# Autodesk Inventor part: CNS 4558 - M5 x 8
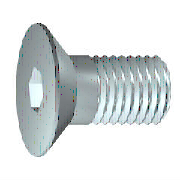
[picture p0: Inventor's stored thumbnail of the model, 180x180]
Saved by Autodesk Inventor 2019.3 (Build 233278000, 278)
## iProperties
Created: 2018-01
Part Number: CNS 4558 - M5 x 8
Material: Ocel, měkká
Description: Šroub se zápustnou hlavou
Document SubType Name: Modeling
Standard: CNS 4558
Designer: B-hon
Standards Organization: CNS
Language: cs-CZ
Size Designation: M5 x 8
Categories: <MemberInstance><Categories><Category DisplayName="Spojovací materiál" InternalName="e4da775c-781d-43d5-af7c-5136215cf5a6" Mnemonic="FSTN"><Category DisplayName
Density: 7.85 g/cm^3
Appearance: Pololeštěná
IsCustomPart: 0
Author: B-hon
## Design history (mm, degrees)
body "Solid1"
revolve "Těleso" stored, may be unused: angle "d13" = 90 deg
sketch "Náčrt2"
  geometry: L1 (0, -7)-(0, 7) reference; L2 (-7, 0)-(7, 0) reference; L3 (1.732, 0)-(0.866, -1.5); L4 (0.866, -1.5)-(-0.866, -1.5); L5 (-0.866, -1.5)-(-1.732, 0); L6 (-1.732, 0)-(-0.866, 1.5); L7 (-0.866, 1.5)-(0.866, 1.5); L8 (0.866, 1.5)-(1.732, 0); A1 r 1.732 centre (0, 0) between (0, 1.732) and (1.732, 0) reference; 2 further points
  constraints: 12 end point, 2 coincident, 2 point on circle, 2 point on line, 12 other
extrude "Drážka" join sketch "Náčrt2" taper "d14" = 0 deg; stored distance "d30" = 10
feature "Závit" dims "d15" = 2.8 (= GEL), "d16" = 0
chamfer "Zkosení1" distance "d17" = 0.49076 (= -0.5 x SPD + 0.5 x GD); stored, may be unused: second distance "d18" = 0.49076 (= GUL), angle "d39" = 45 deg
workplane "Work Plane1"
sketch "Náčrt1"
  geometry: L1 (8, 0)-(8, 2.5); L2 (8, 2.5)-(5.2, 2.5); L3 (5.2, 2.5)-(4.709, 2.5); L4 (0, 5)-(0, 1.732); L5 (0, 1.732)-(2.3, 1.732); L6 (2.3, 1.732)-(3.3, 0); L7 (3.3, 0)-(8, 0); L8 (0, 5)-(0.3, 5); L9 (0.3, 5)-(2.8, 2.5); L10 (4.709, 2.5)-(2.8, 2.5); L11 (5.2, 2.5)-(2.8, 2.5); L12 (2.8, 2.5)-(2.8, 2.5); L13 (-1.6, 0)-(9.6, 0) reference; L14 (0, -1)-(0, 6) reference
  constraints: 24 end point, 4 collinear, 3 parallel
  dimensions: "d0" = 8 distance between parallel lines of L4 L1 (= NLG); "d1" = 2.8 distance from line of L2.end L1 (= GEL); "d2" = 2.3 distance from line of L5.end L4 (= INTI); "d3" = 5 diameter of L2 L7 (= GD); "d6" = 2.8 distance from line of L9.end L4 (= KOH); "d7" = 45 deg angle of L9 L7 (= 0.5 x SEWI); "d8" = 3.4641 diameter of L5 L7 (= 1.1547 x SW); "d9" = 60 deg angle of L6 L7; "d10" = 10 diameter of L8 L7 (= KOD); "d11" = 5 diameter of L10 L7 (= BDM); "d12" = 0.49076 distance of L3.end L2.end (= GAL)
other parameters: "NLG" = 8 [user parameter; used in 1 equation term], "INTI" = 2.3 [user parameter; used in 1 equation term], "GEL" = 2.8 [user parameter; used in 2 equation terms], "GAL" = 0.49076 (= 0.61345 x PTC) [user parameter; used in 1 equation term], "KOH" = 2.8 [user parameter; used in 1 equation term], "KOD" = 10 [user parameter; used in 1 equation term], "GUL" = 0.49076 (= 0.61345 x PTC) [user parameter; used in 1 equation term], "SPD" = 4.01848 (= NND - 1.2269 x PTC) [user parameter; used in 1 equation term], "BDM" = 5 (= NND) [user parameter; used in 1 equation term], "GD" = 5 (= NND) [user parameter; used in 2 equation terms], "SEWI" = 90 deg [user parameter; used in 1 equation term], "d20" = 0, "SW" = 3 [user parameter; used in 2 equation terms], "d43" = 0, "d44" = 0, "TOA" = 30 deg [user parameter], "GD1" = 4.01848 (= THREADDIA - 1.2269 x PTC) [user parameter], "EPV" = 5.3 [user parameter], "THREADDIA" = 5 [user parameter; used in 1 equation term], "TPU" = 12.5 (computed from PTC) [user parameter], "PTC" = 0.8 [user parameter; used in 5 equation terms], "NND" = 5 [user parameter; used in 3 equation terms], "E0" = 3.465 (= 1.155 x SW) [user parameter]
